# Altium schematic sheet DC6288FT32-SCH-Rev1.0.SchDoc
size A4
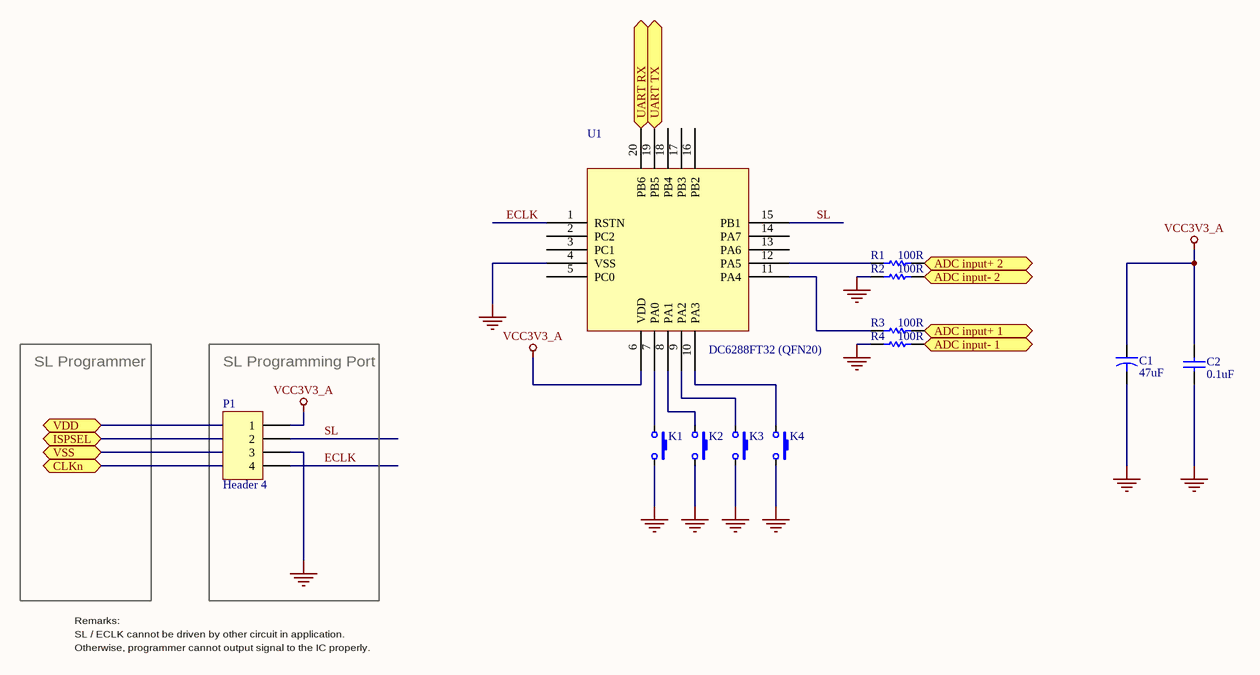
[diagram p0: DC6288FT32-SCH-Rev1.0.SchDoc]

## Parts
C1  value 47uF  [CAPR5-4X5]  (hidden comment: Cap2)
C2  value 0.1uF  [RAD-0.3]  (hidden comment: Cap)
K1  KEYPAD_SW  [DPST-4]  (value not drawn)
K2  KEYPAD_SW  [DPST-4]  (value not drawn)
K3  KEYPAD_SW  [DPST-4]  (value not drawn)
K4  KEYPAD_SW  [DPST-4]  (value not drawn)
P1  Header 4  [HDR1X4]
R1  value 100R  [AXIAL-0.3]  (hidden comment: Res1)
R2  value 100R  [AXIAL-0.3]  (hidden comment: Res1)
R3  value 100R  [AXIAL-0.3]  (hidden comment: Res1)
R4  value 100R  [AXIAL-0.3]  (hidden comment: Res1)
U1  DC6288FT32 (QFN20)  [OTS-28-0.65-01]

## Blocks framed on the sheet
SL Programming Port: P1

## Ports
ADC input+ 1, ADC input+ 2, ADC input- 1, ADC input- 2, CLKn, ISPSEL, UART RX, UART TX, VDD, VSS

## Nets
GND: C1.2 C2.1 K1.2 K2.2 K3.2 K4.2 P1.3 R2.2 R4.2 U1.4(VSS)
VCC3V3_A: C1.1 C2.2 P1.1 U1.6(VDD)
ADC input+ 1: R3.1 ; port ADC input+ 1
ADC input+ 2: R1.1 ; port ADC input+ 2
ADC input- 1: R4.1 ; port ADC input- 1
ADC input- 2: R2.1 ; port ADC input- 2
ECLK: P1.4 U1.1(RSTN)
SL: P1.2 U1.15(PB1)
UART RX: U1.20(PB6) ; port UART RX
UART TX: U1.19(PB5) ; port UART TX
NetK1_1: K1.1 U1.7(PA0)
NetK2_1: K2.1 U1.8(PA1)
NetK3_1: K3.1 U1.9(PA2)
NetK4_1: K4.1 U1.10(PA3)
NetR1_2: R1.2 U1.12(PA5)
NetR3_2: R3.2 U1.11(PA4)

Not connected (* = marked no-connect by the designer): U1 2(PC2) 3(PC1) 5(PC0) 13(PA6) 14(PA7) 16(PB2) 17(PB3) 18(PB4)

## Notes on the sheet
- SL Programmer
- Remarks:
- SL / ECLK cannot be driven by other circuit in application.
- Otherwise, programmer cannot output signal to the IC properly.

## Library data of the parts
C1 = Cap2: Capacitor; Manufacturer: Generic Components; Class I: Passive
C2 = Cap: Capacitor; Manufacturer: Generic Components; Class I: Passive
P1 = Header 4: Header, 4-Pin
R1-R4 = Res1: Resistor; Manufacturer: Generic Components; Class I: Passive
